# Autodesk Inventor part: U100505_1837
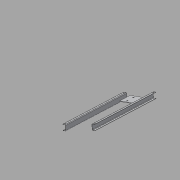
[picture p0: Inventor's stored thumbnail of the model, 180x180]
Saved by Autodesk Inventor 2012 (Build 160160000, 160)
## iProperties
Company: CAD-Verlag
Part Number: U100505_1837
Document SubType Name: Modeling
Created: 2004-09
Material: Standard
Designer: Greiling
Manufacturer: Standard
Standards Organization: Custom
Density: 1 g/cm^3
Control State: 0
Master: False
Checked Out: False
Shininess: 64.0
Length Units: 11269
Angle Units: 11279
Time Units: 11290
Mass Units: 11283
Length Display Precision: 3
Angle Display Precision: 2
Compacted: True
Density: 0.0
Volumn: 0.0
Area: 0.0
PropertySet Name: Model Information
Author: Jürgen Kronas
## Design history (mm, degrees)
sketch "Skizze1"
  geometry: L1 (0, 134.142)-(0, -13.107) reference; L2 (-57.848, 0)-(15.777, 0) reference; L3 (-57.848, 0)-(15.777, 0) reference; L4 (0, -13.107)-(0, 134.142) reference; L5 (0, 100)-(-37.5, 100); L6 (-50, 87.5)-(-50, 12.5); L7 (-37.5, 0)-(0, 0); L8 (0, 0)-(0, 5); L9 (0, 5)-(-37.5, 5); L10 (-45, 12.5)-(-45, 87.5); L11 (-37.5, 95)-(0, 95); L12 (0, 95)-(0, 100); A1 r 12.5 centre (-37.5, 87.5) between (-37.5, 100) and (-50, 87.5); A2 r 12.5 centre (-37.5, 12.5) between (-50, 12.5) and (-37.5, 0); A3 r 7.5 centre (-37.5, 12.5) between (-45, 12.5) and (-37.5, 5); A4 r 7.5 centre (-37.5, 87.5) between (-37.5, 95) and (-45, 87.5); 1 further point
  constraints: 16 end point, 8 point on circle, 4 centre point, 3 point on line
extrude "Extrusion1" new body sketch "Skizze1" distance "d0" = 1637; taper "d1" = 0 deg
sketch "Skizze2"
  geometry: L1 (0, -1637)-(37.5, -1637) reference; L2 (37.5, 0)-(0, 0) reference; L3 (0, 0)-(0, -1637) reference; L4 (-12.5, 0)-(-12.5, -1637) reference; 2 further points
  dimensions: "d2" = 35 distance from line of L2 point (17.5, -35); "d3" = 35 distance from line of L1 point (17.5, -1602); "d4" = 30 distance from line of L4 point (17.5, -1602); "d5" = 30 distance from line of L4 point (17.5, -35)
hole "Bohrung1" sketch "Skizze2" at (17.5, -35), (17.5, -1602) diameter "d6" = 14; stored, may be unused: countersink angle "d10" = 82 deg, drill point angle "d12" = 118 deg; dims "d7" = 6, "d8" = 4, "d9" = 2, "d11" = 8
node "Volumenkörper1"
node "Volumenkörpern"
node "Oberflächenkörpern"
